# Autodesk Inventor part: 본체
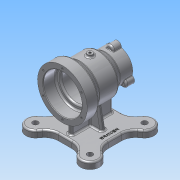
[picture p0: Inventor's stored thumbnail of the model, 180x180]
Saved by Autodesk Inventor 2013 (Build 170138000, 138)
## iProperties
Created: 2017-03
Part Number: 본체
Material: 알루미늄 6061
Document SubType Name: Modeling
Designer: Administrator
Density: 2.71 g/cm^3
Mass: 1011.14 g
Surface Area: 837.658 cm^2
Volume: 373.114 cm^3
Author: Administrator
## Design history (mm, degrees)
sketch "스케치1" dims "d0" = 140
  geometry: L1 (45, -45)-(45, 45); L2 (45, 45)-(-45, 45); L3 (-45, 45)-(-45, -45); L4 (-45, -45)-(45, -45); L5 (45, -45)-(-45, 45); L6 (45, 45)-(-45, -45); L7 (59.97, 36.106)-(45, 24.4); L8 (-59.97, -36.106)-(-45, -24.4); L9 (59.97, -36.106)-(45, -24.4); L10 (-59.97, 36.106)-(-45, 24.4); L11 (-36.106, 59.97)-(-24.4, 45); L12 (36.106, 59.97)-(24.4, 45); L13 (-36.106, -59.97)-(-24.4, -45); L14 (36.106, -59.97)-(24.4, -45); A1 r 17 centre (-49.497, 49.497) between (-59.97, 36.106) and (-36.106, 59.97); A2 r 17 centre (49.497, 49.497) between (59.97, 36.106) and (36.106, 59.97); A3 r 17 centre (-49.497, -49.497) between (-59.97, -36.106) and (-36.106, -59.97); A4 r 17 centre (49.497, -49.497) between (59.97, -36.106) and (36.106, -59.97); 2 further points
  constraints: 28 end point, 9 point on line, 8 point on circle, 7 tangent, 4 centre point, 3 equal radius, 3 parallel, 2 midpoint, 1 coincident, 1 perpendicular, 1 vertical, 14 other
  dimensions: "d2" = 90 distance of L1.end L2.end; "d3" = 90 distance of L1.start L1.end; "d4" = 90 deg dimension on point (0, 0) A2.centre A1.centre; "d5" = 90 deg dimension on point (0, 0) A4.centre A3.centre; "d6" = 90 deg dimension on point (0, 0) A2.centre A4.centre; "d7" = 34 diameter of A1
extrude "돌출1" new body sketch "스케치1" distance "d8" = 12; taper "d9" = 0 deg
fillet "모깎기1" dims "d10" = 25
fillet "모깎기2" dims "d11" = 25
fillet "모깎기3" dims "d12" = 25
fillet "모깎기4" dims "d13" = 3
sketch "스케치2"
  geometry: L1 (-50, 82)-(50, 82); L2 (-31.907, 0)-(-12.213, 0) reference; L3 (-50, 127)-(-30, 127); L4 (-30, 127)-(-19, 118); L5 (-19, 118)-(15, 118); L6 (15, 118)-(27, 109.5); L7 (27, 109.5)-(50, 109.5); L8 (50, 109.5)-(50, 99.5); L9 (50, 99.5)-(20, 99.5); L10 (20, 99.5)-(20, 108); L11 (20, 108)-(-27, 108); L12 (-27, 108)-(-27, 117); L13 (-27, 117)-(-50, 117); L14 (-50, 117)-(-50, 127); 2 further points
  constraints: 26 end point, 9 parallel, 3 vertical alignment, 1 horizontal, 1 midpoint, 1 perpendicular
  dimensions: "d14" = 82 distance between parallel lines of L2 L1; "d15" = 100 distance of L1.start L1.end; "d16" = 35 diameter of L9 L1; "d17" = 52 diameter of L11 L1; "d18" = 70 diameter of L13 L1; "d19" = 55 diameter of L7 L1; "d20" = 72 diameter of L5 L1; "d21" = 90 diameter of L3 L1; "d22" = 20 distance from line of L3.end L14; "d23" = 31 distance from line of L4.end L14; "d24" = 65 distance from line of L5.end L14; "d25" = 23 distance from line of L8 L6.end; "d26" = 23 distance between parallel lines of L12 L14; "d27" = 47 distance between parallel lines of L10 L12
revolve "회전1" sketch "스케치2" stored, may be unused: angle "d28" = 90 deg
sketch "스케치3"
  geometry: L1 (42, 12.213)-(42, -12.213) reference; L2 (-37, 4)-(37, 4); L3 (37, 4)-(37, -4); L4 (37, -4)-(-37, -4); L5 (-37, -4)-(-37, 4); L6 (-37, 4)-(37, -4); L7 (37, 4)-(-37, -4); 1 further point
  constraints: 12 end point, 2 midpoint, 2 parallel, 2 perpendicular
  dimensions: "d29" = 8 distance between parallel lines of L4 L2; "d31" = 37 distance from line of point (0, 0) L3
extrude "돌출2" join sketch "스케치3" stored distance "d32" = 12; taper "d33" = 0 deg
sketch "스케치4"
  geometry: L1 (34.27, 12)-(12.213, 12) reference; L2 (38.469, 12)-(34.27, 12) reference; L3 (-12.213, 12)-(-34.27, 12) reference; L4 (-34.27, 12)-(-38.469, 12) reference; L5 (25, 12)-(16.238, 61.694); L6 (-25, 12)-(-16.238, 61.694); L7 (12.213, 12)-(-12.213, 12) reference; L8 (4, 12)-(4, 37.178) reference; L9 (4, 37.178)-(4, 46.223) reference; L10 (-4, 46.223)-(-4, 37.178) reference; L11 (-4, 12)-(-4, 37.178) reference; A1 r 26 centre (0, 82) between (16.238, 61.694) and (-16.238, 61.694) reference; 1 further point
  constraints: 4 end point, 2 point on circle, 2 point on line
  dimensions: "d34" = 25 horizontal distance of point (0, 0) L5.start; "d35" = 25 horizontal distance of L6.start point (0, 0); "d36" = 100 deg angle of L1 L5; "d37" = 100 deg angle of L3 L6
extrude "돌출3" join sketch "스케치4" stored distance "d38" = 8; taper "d39" = 0 deg
fillet "모깎기5" dims "d40" = 3
fillet "모깎기6" dims "d41" = 3
fillet "모깎기7" dims "d42" = 3
fillet "모깎기8" dims "d43" = 3
fillet "모깎기9" dims "d44" = 3
fillet "모깎기10" dims "d45" = 3
chamfer "모따기1" distance "d46" = 1; stored, may be unused: second distance "d47" = 2, angle "d48" = 45 deg
node "작업 평면1"
sketch "스케치5"
  geometry: C1 r 5 at (0, 0); 1 further point
  constraints: 1 centre point, 1 coincident
  dimensions: "d50" = 10 diameter of C1
extrude "돌출4" join sketch "스케치5" stored distance "d52" = 8; taper "d53" = 0 deg
sketch "스케치6"
  geometry: C1 r 5 at (0, 0) reference; 1 further point
  constraints: 1 coincident
hole "구멍1" sketch "스케치6" at (0, 0) diameter "d54" = 4.134; stored, may be unused: countersink angle "d58" = 90 deg, drill point angle "d60" = 118 deg; dims "d55" = 6, "d56" = 4, "d57" = 2, "d59" = 8
fillet "모깎기11" dims "d61" = 3
sketch "스케치7"
  geometry: C1 r 7 at (27.5, 0); 2 further points
  constraints: 2 horizontal alignment, 1 centre point, 1 other
  dimensions: "d62" = 14 diameter of C1
extrude "돌출5" join sketch "스케치7" distance "d64" = 15; taper "d65" = 0 deg
sketch "스케치8"
  geometry: A1 r 7 centre (0, 0) between (-0.891, -6.943) and (-0.891, 6.943) reference; A2 r 7 centre (-41.25, 23.816) between (-34.792, 26.516) and (-46.817, 19.573) reference; A3 r 7 centre (-41.25, -23.816) between (-46.817, -19.573) and (-34.792, -26.516) reference; 4 further points
  constraints: 3 coincident
hole "구멍2" sketch "스케치8" at (-41.25, 23.816), (-41.25, -23.816), (0, 0) diameter "d69" = 3.242; stored, may be unused: countersink angle "d73" = 90 deg, drill point angle "d75" = 118 deg; dims "d70" = 9, "d71" = 4, "d72" = 2, "d74" = 11
fillet "모깎기12" dims "d76" = 1
fillet "모깎기13" dims "d77" = 3
fillet "모깎기14" dims "d78" = 1
sketch "스케치9" dims "d79" = 80
  geometry: C1 r 45 at (0, 0) reference; C2 r 36 at (0, 0) reference; 2 further points
  constraints: 2 horizontal alignment, 2 other
hole "구멍3" sketch "스케치9" at (-40, 0) diameter "d81" = 3.242; stored, may be unused: countersink angle "d85" = 90 deg, drill point angle "d87" = 118 deg; dims "d82" = 9, "d83" = 4, "d84" = 2, "d86" = 11
node "작업 평면2"
sketch "스케치10"
  geometry: L1 (-45, 12.213)-(-45, -12.213) reference; 2 further points
  constraints: 1 other
  dimensions: "d92" = 35 distance of point (0, 0) point (0, 35); "d93" = 45 distance from line of L1 point (0, 35)
feature "엠보싱1" sketch "스케치10" dims "d0" = 140, "d2" = 90, "d3" = 90, "d4" = 90 deg, "d5" = 90 deg, "d6" = 90 deg, "d7" = 34, "d94" = 0.5, "d95" = 0
sketch "스케치11"
  geometry: C1 r 5 at (-49.497, -49.497); C2 r 5 at (-49.497, 49.497); C3 r 5 at (49.497, 49.497); C4 r 5 at (49.497, -49.497); A1 r 14 centre (-49.497, -49.497) between (-58.122, -38.469) and (-38.469, -58.122) reference; A2 r 14 centre (49.497, -49.497) between (38.469, -58.122) and (58.122, -38.469) reference; A3 r 14 centre (49.497, 49.497) between (58.122, 38.469) and (38.469, 58.122) reference; A4 r 14 centre (-49.497, 49.497) between (-38.469, 58.122) and (-58.122, 38.469) reference; 1 further point
  constraints: 4 centre point, 4 coincident, 3 equal radius
  dimensions: "d96" = 10 diameter of C2
extrude "돌출6" cut sketch "스케치11" stored distance "d98" = 10; taper "d99" = 0 deg
node "솔리드1"
pattern_circular "원형 패턴1" dims angle "d67" = 360 deg
pattern_circular "원형 패턴2" dims angle "d89" = 360 deg
other parameters: "d49" = 122, "d91" = 31.75
